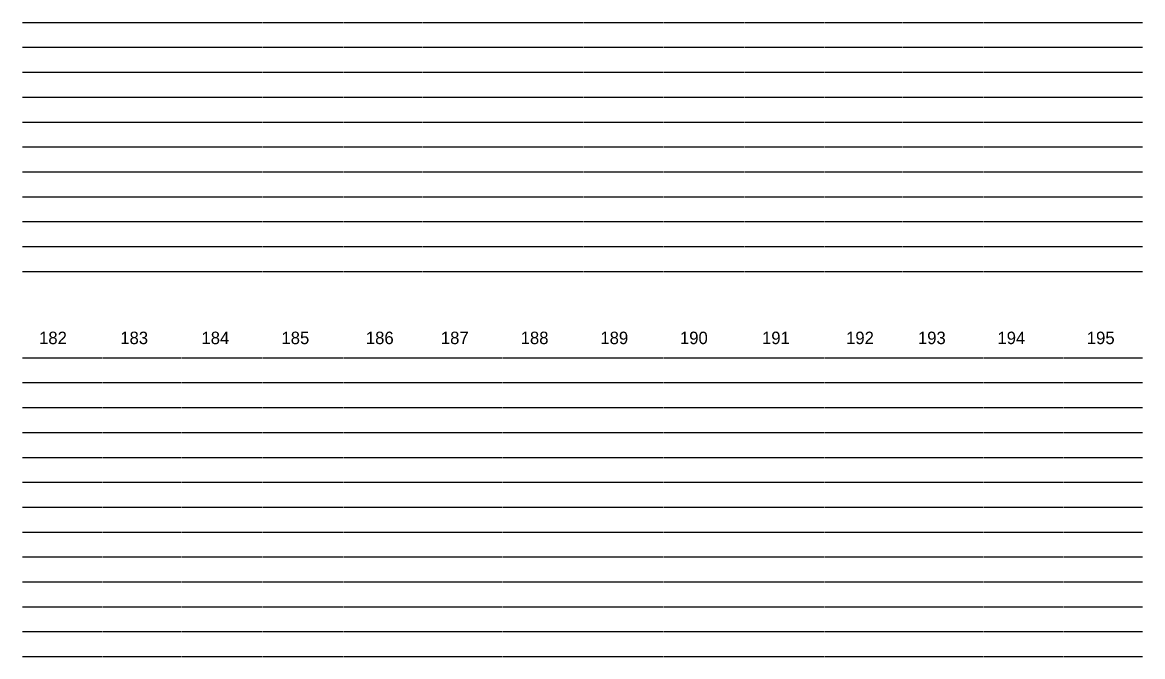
# Model space of a CAD drawing. Extents: x 11193 to 12507, y 10092 to 10555.
# Drawn here: x 11448.5 to 11643.4, y 10092.8 to 10203.2 of the extents above; entities that cross this region are included whole.
import ezdxf

# ---------------------------------------------------------------- set-up
doc = ezdxf.new("R2010")
doc.units = 0
doc.layers.add('Level 2', color=7, linetype='Continuous')

msp = doc.modelspace()

# ---------------------------------------------------------------- linework, layer by layer
at = {"layer": 'Level 2'}
for p, q in [((11448.48, 10203.17), (11462.4, 10203.17)), ((11462.5, 10203.17), (11476.08, 10203.17)), ((11476.18, 10203.17), (11490.16, 10203.17)), ((11490.26, 10203.17), (11504.24, 10203.17)), ((11504.35, 10203.17), (11518.12, 10203.17)), ((11518.23, 10203.17), (11532, 10203.17)), ((11532.11, 10203.17), (11546.08, 10203.17)), ((11546.19, 10203.17), (11559.97, 10203.17)), ((11560.08, 10203.17), (11574.05, 10203.17)), ((11574.15, 10203.17), (11587.93, 10203.17)), ((11588.04, 10203.17), (11601.6, 10203.17)), ((11601.71, 10203.17), (11615.68, 10203.17)), ((11615.79, 10203.17), (11629.57, 10203.17)), ((11629.68, 10203.17), (11643.42, 10203.17)), ((11448.48, 10198.84), (11462.4, 10198.84)), ((11462.5, 10198.84), (11476.08, 10198.84)), ((11476.18, 10198.84), (11490.16, 10198.84)), ((11490.26, 10198.84), (11504.24, 10198.84)), ((11504.35, 10198.84), (11518.12, 10198.84)), ((11518.23, 10198.84), (11532, 10198.84)), ((11532.11, 10198.84), (11546.08, 10198.84)), ((11546.19, 10198.84), (11559.97, 10198.84)), ((11560.08, 10198.84), (11574.05, 10198.84)), ((11574.15, 10198.84), (11587.93, 10198.84)), ((11588.04, 10198.84), (11601.6, 10198.84)), ((11601.71, 10198.84), (11615.68, 10198.84)), ((11615.79, 10198.84), (11629.57, 10198.84)), ((11629.68, 10198.84), (11643.42, 10198.84)), ((11448.48, 10194.51), (11462.4, 10194.51)), ((11462.5, 10194.51), (11476.08, 10194.51)), ((11476.18, 10194.51), (11490.16, 10194.51)), ((11490.26, 10194.51), (11504.24, 10194.51)), ((11504.35, 10194.51), (11518.12, 10194.51)), ((11518.23, 10194.51), (11532, 10194.51)), ((11532.11, 10194.51), (11546.08, 10194.51)), ((11546.19, 10194.51), (11559.97, 10194.51)), ((11560.08, 10194.51), (11574.05, 10194.51)), ((11574.15, 10194.51), (11587.93, 10194.51)), ((11588.04, 10194.51), (11601.6, 10194.51)), ((11601.71, 10194.51), (11615.68, 10194.51)), ((11615.79, 10194.51), (11629.57, 10194.51)), ((11629.68, 10194.51), (11643.42, 10194.51)), ((11448.48, 10190.17), (11462.4, 10190.17)), ((11462.5, 10190.17), (11476.08, 10190.17)), ((11476.18, 10190.17), (11490.16, 10190.17)), ((11490.26, 10190.17), (11504.24, 10190.17)), ((11504.35, 10190.17), (11518.12, 10190.17)), ((11518.23, 10190.17), (11532, 10190.17)), ((11532.11, 10190.17), (11546.08, 10190.17)), ((11546.19, 10190.17), (11559.97, 10190.17)), ((11560.08, 10190.17), (11574.05, 10190.17)), ((11574.15, 10190.17), (11587.93, 10190.17)), ((11588.04, 10190.17), (11601.6, 10190.17)), ((11601.71, 10190.17), (11615.68, 10190.17)), ((11615.79, 10190.17), (11629.57, 10190.17)), ((11629.68, 10190.17), (11643.42, 10190.17)), ((11448.48, 10185.84), (11462.4, 10185.84)), ((11462.5, 10185.84), (11476.08, 10185.84)), ((11476.18, 10185.84), (11490.16, 10185.84)), ((11490.26, 10185.84), (11504.24, 10185.84)), ((11504.35, 10185.84), (11518.12, 10185.84)), ((11518.23, 10185.84), (11532, 10185.84)), ((11532.11, 10185.84), (11546.08, 10185.84)), ((11546.19, 10185.84), (11559.97, 10185.84)), ((11560.08, 10185.84), (11574.05, 10185.84)), ((11574.15, 10185.84), (11587.93, 10185.84)), ((11588.04, 10185.84), (11601.6, 10185.84)), ((11601.71, 10185.84), (11615.68, 10185.84)), ((11615.79, 10185.84), (11629.57, 10185.84)), ((11629.68, 10185.84), (11643.42, 10185.84)), ((11448.48, 10181.51), (11462.4, 10181.51)), ((11462.5, 10181.51), (11476.08, 10181.51)), ((11476.18, 10181.51), (11490.16, 10181.51)), ((11490.26, 10181.51), (11504.24, 10181.51)), ((11504.35, 10181.51), (11518.12, 10181.51)), ((11518.23, 10181.51), (11532, 10181.51)), ((11532.11, 10181.51), (11546.08, 10181.51)), ((11546.19, 10181.51), (11559.97, 10181.51)), ((11560.08, 10181.51), (11574.05, 10181.51)), ((11574.15, 10181.51), (11587.93, 10181.51)), ((11588.04, 10181.51), (11601.6, 10181.51)), ((11601.71, 10181.51), (11615.68, 10181.51)), ((11615.79, 10181.51), (11629.57, 10181.51)), ((11629.68, 10181.51), (11643.42, 10181.51)), ((11448.48, 10177.18), (11462.4, 10177.18)), ((11462.5, 10177.18), (11476.08, 10177.18)), ((11476.18, 10177.18), (11490.16, 10177.18)), ((11490.26, 10177.18), (11504.24, 10177.18)), ((11504.35, 10177.18), (11518.12, 10177.18)), ((11518.23, 10177.18), (11532, 10177.18)), ((11532.11, 10177.18), (11546.08, 10177.18)), ((11546.19, 10177.18), (11559.97, 10177.18)), ((11560.08, 10177.18), (11574.05, 10177.18)), ((11574.15, 10177.18), (11587.93, 10177.18)), ((11588.04, 10177.18), (11601.6, 10177.18)), ((11601.71, 10177.18), (11615.68, 10177.18)), ((11615.79, 10177.18), (11629.57, 10177.18)), ((11629.68, 10177.18), (11643.42, 10177.18)), ((11448.48, 10172.85), (11462.4, 10172.85)), ((11462.5, 10172.85), (11476.08, 10172.85)), ((11476.18, 10172.85), (11490.16, 10172.85)), ((11490.26, 10172.85), (11504.24, 10172.85)), ((11504.35, 10172.85), (11518.12, 10172.85)), ((11518.23, 10172.85), (11532, 10172.85)), ((11532.11, 10172.85), (11546.08, 10172.85)), ((11546.19, 10172.85), (11559.97, 10172.85)), ((11560.08, 10172.85), (11574.05, 10172.85)), ((11574.15, 10172.85), (11587.93, 10172.85)), ((11588.04, 10172.85), (11601.6, 10172.85)), ((11601.71, 10172.85), (11615.68, 10172.85)), ((11615.79, 10172.85), (11629.57, 10172.85)), ((11629.68, 10172.85), (11643.42, 10172.85)), ((11448.48, 10168.51), (11462.4, 10168.51)), ((11462.5, 10168.51), (11476.08, 10168.51)), ((11476.18, 10168.51), (11490.16, 10168.51)), ((11490.26, 10168.51), (11504.24, 10168.51)), ((11504.35, 10168.51), (11518.12, 10168.51)), ((11518.23, 10168.51), (11532, 10168.51)), ((11532.11, 10168.51), (11546.08, 10168.51)), ((11546.19, 10168.51), (11559.97, 10168.51)), ((11560.08, 10168.51), (11574.05, 10168.51)), ((11574.15, 10168.51), (11587.93, 10168.51)), ((11588.04, 10168.51), (11601.6, 10168.51)), ((11601.71, 10168.51), (11615.68, 10168.51)), ((11615.79, 10168.51), (11629.57, 10168.51)), ((11629.68, 10168.51), (11643.42, 10168.51)), ((11448.48, 10164.18), (11462.4, 10164.18)), ((11462.5, 10164.18), (11476.08, 10164.18)), ((11476.18, 10164.18), (11490.16, 10164.18)), ((11490.26, 10164.18), (11504.24, 10164.18)), ((11504.35, 10164.18), (11518.12, 10164.18)), ((11518.23, 10164.18), (11532, 10164.18)), ((11532.11, 10164.18), (11546.08, 10164.18)), ((11546.19, 10164.18), (11559.97, 10164.18)), ((11560.08, 10164.18), (11574.05, 10164.18)), ((11574.15, 10164.18), (11587.93, 10164.18)), ((11588.04, 10164.18), (11601.6, 10164.18)), ((11601.71, 10164.18), (11615.68, 10164.18)), ((11615.79, 10164.18), (11629.57, 10164.18)), ((11629.68, 10164.18), (11643.42, 10164.18)), ((11448.48, 10159.85), (11462.4, 10159.85)), ((11462.5, 10159.85), (11476.08, 10159.85)), ((11476.18, 10159.85), (11490.16, 10159.85)), ((11490.26, 10159.85), (11504.24, 10159.85)), ((11504.35, 10159.85), (11518.12, 10159.85)), ((11518.23, 10159.85), (11532, 10159.85)), ((11532.11, 10159.85), (11546.08, 10159.85)), ((11546.19, 10159.85), (11559.97, 10159.85)), ((11560.08, 10159.85), (11574.05, 10159.85)), ((11574.15, 10159.85), (11587.93, 10159.85)), ((11588.04, 10159.85), (11601.6, 10159.85)), ((11601.71, 10159.85), (11615.68, 10159.85)), ((11615.79, 10159.85), (11629.57, 10159.85)), ((11629.68, 10159.85), (11643.42, 10159.85)), ((11448.48, 10144.83), (11462.41, 10144.83)), ((11462.53, 10144.83), (11476.09, 10144.83)), ((11476.2, 10144.83), (11490.17, 10144.83)), ((11490.29, 10144.83), (11504.25, 10144.83)), ((11504.37, 10144.83), (11518.14, 10144.83)), ((11518.25, 10144.83), (11532.02, 10144.83)), ((11532.12, 10144.83), (11546.1, 10144.83)), ((11546.2, 10144.83), (11559.98, 10144.83)), ((11560.08, 10144.83), (11574.07, 10144.83)), ((11574.17, 10144.83), (11587.94, 10144.83)), ((11588.04, 10144.83), (11601.62, 10144.83)), ((11601.72, 10144.83), (11615.7, 10144.83)), ((11615.8, 10144.83), (11629.58, 10144.83)), ((11629.69, 10144.83), (11643.42, 10144.83)), ((11448.48, 10140.5), (11462.41, 10140.5)), ((11462.53, 10140.5), (11476.09, 10140.5)), ((11476.2, 10140.5), (11490.17, 10140.5)), ((11490.29, 10140.5), (11504.25, 10140.5)), ((11504.37, 10140.5), (11518.14, 10140.5)), ((11518.25, 10140.5), (11532.02, 10140.5)), ((11532.12, 10140.5), (11546.1, 10140.5)), ((11546.2, 10140.5), (11559.98, 10140.5)), ((11560.08, 10140.5), (11574.07, 10140.5)), ((11574.17, 10140.5), (11587.94, 10140.5)), ((11588.04, 10140.5), (11601.62, 10140.5)), ((11601.72, 10140.5), (11615.7, 10140.5)), ((11615.8, 10140.5), (11629.58, 10140.5)), ((11629.69, 10140.5), (11643.42, 10140.5)), ((11448.48, 10136.16), (11462.41, 10136.16)), ((11462.53, 10136.16), (11476.09, 10136.16)), ((11476.2, 10136.16), (11490.17, 10136.16)), ((11490.29, 10136.16), (11504.25, 10136.16)), ((11504.37, 10136.16), (11518.14, 10136.16)), ((11518.25, 10136.16), (11532.02, 10136.16)), ((11532.12, 10136.16), (11546.1, 10136.16)), ((11546.2, 10136.16), (11559.98, 10136.16)), ((11560.08, 10136.16), (11574.07, 10136.16)), ((11574.17, 10136.16), (11587.94, 10136.16)), ((11588.04, 10136.16), (11601.62, 10136.16)), ((11601.72, 10136.16), (11615.7, 10136.16)), ((11615.8, 10136.16), (11629.58, 10136.16)), ((11629.69, 10136.16), (11643.42, 10136.16)), ((11448.48, 10131.83), (11462.41, 10131.83)), ((11462.53, 10131.83), (11476.09, 10131.83)), ((11476.2, 10131.83), (11490.17, 10131.83)), ((11490.29, 10131.83), (11504.25, 10131.83)), ((11504.37, 10131.83), (11518.14, 10131.83)), ((11518.25, 10131.83), (11532.02, 10131.83)), ((11532.12, 10131.83), (11546.1, 10131.83)), ((11546.2, 10131.83), (11559.98, 10131.83)), ((11560.08, 10131.83), (11574.07, 10131.83)), ((11574.17, 10131.83), (11587.94, 10131.83)), ((11588.04, 10131.83), (11601.62, 10131.83)), ((11601.72, 10131.83), (11615.7, 10131.83)), ((11615.8, 10131.83), (11629.58, 10131.83)), ((11629.69, 10131.83), (11643.42, 10131.83)), ((11448.48, 10127.5), (11462.41, 10127.5)), ((11462.53, 10127.5), (11476.09, 10127.5)), ((11476.2, 10127.5), (11490.17, 10127.5)), ((11490.29, 10127.5), (11504.25, 10127.5)), ((11504.37, 10127.5), (11518.14, 10127.5)), ((11518.25, 10127.5), (11532.02, 10127.5)), ((11532.12, 10127.5), (11546.1, 10127.5)), ((11546.2, 10127.5), (11559.98, 10127.5)), ((11560.08, 10127.5), (11574.07, 10127.5)), ((11574.17, 10127.5), (11587.94, 10127.5)), ((11588.04, 10127.5), (11601.62, 10127.5)), ((11601.72, 10127.5), (11615.7, 10127.5)), ((11615.8, 10127.5), (11629.58, 10127.5)), ((11629.69, 10127.5), (11643.42, 10127.5)), ((11448.48, 10123.17), (11462.41, 10123.17)), ((11462.53, 10123.17), (11476.09, 10123.17)), ((11476.2, 10123.17), (11490.17, 10123.17)), ((11490.29, 10123.17), (11504.25, 10123.17)), ((11504.37, 10123.17), (11518.14, 10123.17)), ((11518.25, 10123.17), (11532.02, 10123.17)), ((11532.12, 10123.17), (11546.1, 10123.17)), ((11546.2, 10123.17), (11559.98, 10123.17)), ((11560.08, 10123.17), (11574.07, 10123.17)), ((11574.17, 10123.17), (11587.94, 10123.17)), ((11588.04, 10123.17), (11601.62, 10123.17)), ((11601.72, 10123.17), (11615.7, 10123.17)), ((11615.8, 10123.17), (11629.58, 10123.17)), ((11629.69, 10123.17), (11643.42, 10123.17)), ((11448.48, 10118.84), (11462.41, 10118.84)), ((11462.53, 10118.84), (11476.09, 10118.84)), ((11476.2, 10118.84), (11490.17, 10118.84)), ((11490.29, 10118.84), (11504.25, 10118.84)), ((11504.37, 10118.84), (11518.14, 10118.84)), ((11518.25, 10118.84), (11532.02, 10118.84)), ((11532.12, 10118.84), (11546.1, 10118.84)), ((11546.2, 10118.84), (11559.98, 10118.84)), ((11560.08, 10118.84), (11574.07, 10118.84)), ((11574.17, 10118.84), (11587.94, 10118.84)), ((11588.04, 10118.84), (11601.62, 10118.84)), ((11601.72, 10118.84), (11615.7, 10118.84)), ((11615.8, 10118.84), (11629.58, 10118.84)), ((11629.69, 10118.84), (11643.42, 10118.84)), ((11448.48, 10114.5), (11462.41, 10114.5)), ((11462.53, 10114.5), (11476.09, 10114.5)), ((11476.2, 10114.5), (11490.17, 10114.5)), ((11490.29, 10114.5), (11504.25, 10114.5)), ((11504.37, 10114.5), (11518.14, 10114.5)), ((11518.25, 10114.5), (11532.02, 10114.5)), ((11532.12, 10114.5), (11546.1, 10114.5)), ((11546.2, 10114.5), (11559.98, 10114.5)), ((11560.08, 10114.5), (11574.07, 10114.5)), ((11574.17, 10114.5), (11587.94, 10114.5)), ((11588.04, 10114.5), (11601.62, 10114.5)), ((11601.72, 10114.5), (11615.7, 10114.5)), ((11615.8, 10114.5), (11629.58, 10114.5)), ((11629.69, 10114.5), (11643.42, 10114.5)), ((11448.48, 10110.17), (11462.41, 10110.17)), ((11462.53, 10110.17), (11476.09, 10110.17)), ((11476.2, 10110.17), (11490.17, 10110.17)), ((11490.29, 10110.17), (11504.25, 10110.17)), ((11504.37, 10110.17), (11518.14, 10110.17)), ((11518.25, 10110.17), (11532.02, 10110.17)), ((11532.12, 10110.17), (11546.1, 10110.17)), ((11546.2, 10110.17), (11559.98, 10110.17)), ((11560.08, 10110.17), (11574.07, 10110.17)), ((11574.17, 10110.17), (11587.94, 10110.17)), ((11588.04, 10110.17), (11601.62, 10110.17)), ((11601.72, 10110.17), (11615.7, 10110.17)), ((11615.8, 10110.17), (11629.58, 10110.17)), ((11629.69, 10110.17), (11643.42, 10110.17)), ((11448.48, 10105.84), (11462.41, 10105.84)), ((11462.53, 10105.84), (11476.09, 10105.84)), ((11476.2, 10105.84), (11490.17, 10105.84)), ((11490.29, 10105.84), (11504.25, 10105.84)), ((11504.37, 10105.84), (11518.14, 10105.84)), ((11518.25, 10105.84), (11532.02, 10105.84)), ((11532.12, 10105.84), (11546.1, 10105.84)), ((11546.2, 10105.84), (11559.98, 10105.84)), ((11560.08, 10105.84), (11574.07, 10105.84)), ((11574.17, 10105.84), (11587.94, 10105.84)), ((11588.04, 10105.84), (11601.62, 10105.84)), ((11601.72, 10105.84), (11615.7, 10105.84)), ((11615.8, 10105.84), (11629.58, 10105.84)), ((11629.69, 10105.84), (11643.42, 10105.84)), ((11448.48, 10101.51), (11462.41, 10101.51)), ((11462.53, 10101.51), (11476.09, 10101.51)), ((11476.2, 10101.51), (11490.17, 10101.51)), ((11490.29, 10101.51), (11504.25, 10101.51)), ((11504.37, 10101.51), (11518.14, 10101.51)), ((11518.25, 10101.51), (11532.02, 10101.51)), ((11532.12, 10101.51), (11546.1, 10101.51)), ((11546.2, 10101.51), (11559.98, 10101.51)), ((11560.08, 10101.51), (11574.07, 10101.51)), ((11574.17, 10101.51), (11587.94, 10101.51)), ((11588.04, 10101.51), (11601.62, 10101.51)), ((11601.72, 10101.51), (11615.7, 10101.51)), ((11615.8, 10101.51), (11629.58, 10101.51)), ((11629.69, 10101.51), (11643.42, 10101.51)), ((11448.48, 10097.18), (11462.41, 10097.18)), ((11462.53, 10097.18), (11476.09, 10097.18)), ((11476.2, 10097.18), (11490.17, 10097.18)), ((11490.29, 10097.18), (11504.25, 10097.18)), ((11504.37, 10097.18), (11518.14, 10097.18)), ((11518.25, 10097.18), (11532.02, 10097.18)), ((11532.12, 10097.18), (11546.1, 10097.18)), ((11546.2, 10097.18), (11559.98, 10097.18)), ((11560.08, 10097.18), (11574.07, 10097.18)), ((11574.17, 10097.18), (11587.94, 10097.18)), ((11588.04, 10097.18), (11601.62, 10097.18)), ((11601.72, 10097.18), (11615.7, 10097.18)), ((11615.8, 10097.18), (11629.58, 10097.18)), ((11629.69, 10097.18), (11643.42, 10097.18)), ((11448.48, 10092.84), (11462.41, 10092.84)), ((11462.53, 10092.84), (11476.09, 10092.84)), ((11476.2, 10092.84), (11490.17, 10092.84)), ((11490.29, 10092.84), (11504.25, 10092.84)), ((11504.37, 10092.84), (11518.14, 10092.84)), ((11518.25, 10092.84), (11532.02, 10092.84)), ((11532.12, 10092.84), (11546.1, 10092.84)), ((11546.2, 10092.84), (11559.98, 10092.84)), ((11560.08, 10092.84), (11574.07, 10092.84)), ((11574.17, 10092.84), (11587.94, 10092.84)), ((11588.04, 10092.84), (11601.62, 10092.84)), ((11601.72, 10092.84), (11615.7, 10092.84)), ((11615.8, 10092.84), (11629.58, 10092.84)), ((11629.69, 10092.84), (11643.42, 10092.84))]:
    msp.add_line(p, q, dxfattribs=at)

# ---------------------------------------------------------------- texts
for s, p in [('182', (11451.38, 10147.2)), ('183', (11465.51, 10147.2)), ('184', (11479.64, 10147.2)), ('185', (11493.56, 10147.2)), ('186', (11508.25, 10147.2)), ('187', (11521.3, 10147.2)), ('188', (11535.19, 10147.2)), ('189', (11549.06, 10147.2)), ('190', (11562.91, 10147.2)), ('191', (11577.19, 10147.2)), ('192', (11591.82, 10147.2)), ('193', (11604.32, 10147.2)), ('194', (11618.16, 10147.2)), ('195', (11633.71, 10147.2))]:
    msp.add_text(s, height=2.17, dxfattribs=at).set_placement(p)

doc.saveas('drawing.dxf')
